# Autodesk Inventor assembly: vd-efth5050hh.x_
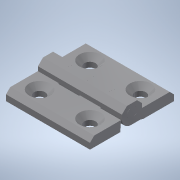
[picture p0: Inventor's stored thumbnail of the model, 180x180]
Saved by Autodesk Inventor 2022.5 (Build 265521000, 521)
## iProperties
Created: 2019-12
Part Number: vd-efth5050hh.x_
Material: 一般
Document SubType Name: Assembly
Designer: ImaoCorp
Sending System: SOLIDWORKS 2018-2018316
MC: AMD64
MC_MODEL: Intel64 Family 6 Model 60 Stepping 3, GenuineIntel
OS: Windows_NT
FRU: Parasolid Version 30.0, build 310,  6- 8-2018
FORMAT: text
GUISE: transmit
KEY: vd-efth5050hh
FILE: vd-efth5050hh.x_t
DATE: Wed Dec 11 13:23:53 2019
Author: ImaoCorp
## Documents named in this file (4)
- X:\14_SW2022-Inv2022\00_全2023-1023新製品(TCC)まで\v\vd-efth5050hh\VD-EFTH5050HH.iam
- X:\14_SW2022-Inv2022\00_全2023-1023新製品(TCC)まで\v\vd-efth5050hh\vd-efth5050hh_01.ipt
- X:\14_SW2022-Inv2022\00_全2023-1023新製品(TCC)まで\v\vd-efth5050hh\vd-efth5050hh_02.ipt
- X:\14_SW2022-Inv2022\00_全2023-1023新製品(TCC)まで\v\vd-efth5050hh\vd-efth5050hh_03.ipt
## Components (3 placed, 3 different names)
1. vd-efth5050hh_01
2. vd-efth5050hh_02
3. vd-efth5050hh_03
